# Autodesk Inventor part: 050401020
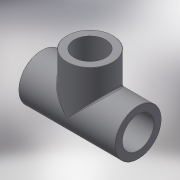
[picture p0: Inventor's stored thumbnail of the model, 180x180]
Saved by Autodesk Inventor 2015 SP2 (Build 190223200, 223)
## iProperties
Created: 2017-10
Part Number: 050401020
Material: Generic
Description: PLASSON THREADED TEE PVC 2"
Document SubType Name: Modeling
Designer: KIM
Density: 1 g/cm^3
Appearance: Default
Author: KIM
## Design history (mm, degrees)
derived "050401.ipt"
feature "Solid1::050401.ipt"
feature "Solid2::050401.ipt"
tag "TaggingFeature1"
body "Solid1"
other parameters: "d0" = 145, "d1" = 73, "d2" = 26, "d4" = 56.656, "d5" = 50.9904, "d7" = 0.56656, "d8" = 26, "d9" = 72.5, "d10" = 73, "d15" = 0, "d18" = 56.656, "d24" = 0.56656, "d30" = 56.656, "d31" = 26, "d32" = 0, "d33" = 50.9904, "d35" = 0, "d36" = 2.8328, "G_" = 56.656, "E_" = 73, "H_" = 145, "lt_" = 26
